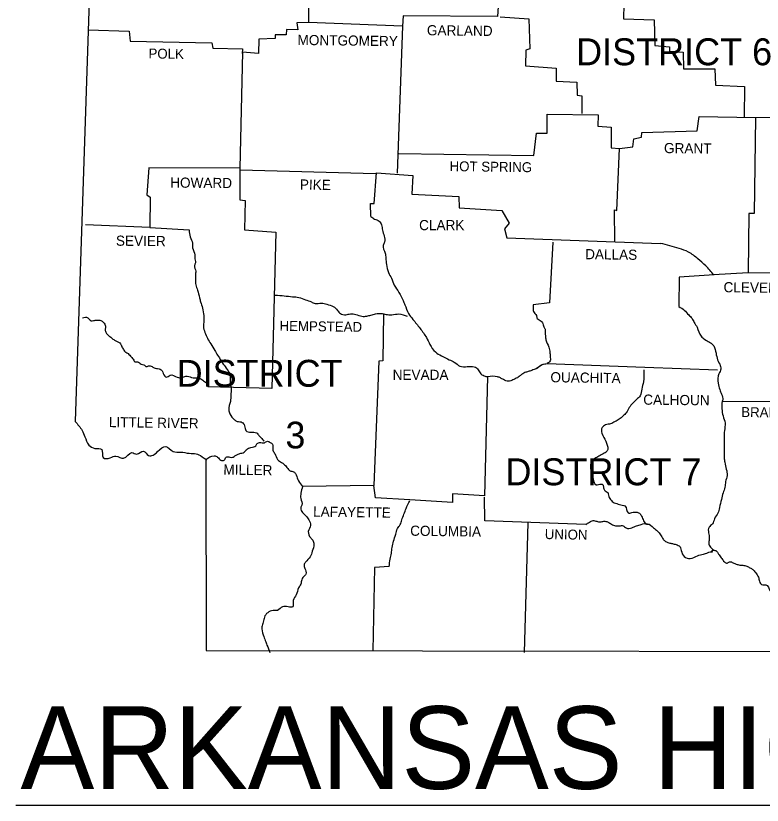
# Model space of a CAD drawing. Extents: x -33639 to 34530, y -17264 to 5867.
# Drawn here: x -17742 to -16002, y -10461 to -8621 of the extents above; entities that cross this region are included whole.
import ezdxf

# ---------------------------------------------------------------- set-up
doc = ezdxf.new("R2010")
doc.units = 0
for name, color, linetype in [('1', 7, 'Continuous'), ('2', 7, 'Continuous'), ('3', 7, 'Continuous'), ('S_MISC_BOUNDARY', 7, 'Continuous')]:
    doc.layers.add(name, color=color, linetype=linetype)

msp = doc.modelspace()

# ---------------------------------------------------------------- linework, layer by layer
at = {"layer": '1'}
msp.add_line((-17741.9, -10460.7), (-14228.8, -10460.7), dxfattribs=at)
for points in [[(-17667.8, -7158.5), (-17553.9, -8073.2), (-17603.4, -9566.3)], [(-17058.6, -8314.8), (-17059.7, -8636.8), (-17087.2, -8637.3), (-17085, -8653.9), (-17111.4, -8653.3), (-17111.9, -8665.4), (-17137.8, -8665.4), (-17137.3, -8674.2), (-17175.8, -8675.3), (-17176.3, -8708.9), (-17213.8, -8705.6), (-17219.8, -8976.4), (-17431.7, -8975.8), (-17436.7, -9038.6), (-17428.9, -9044.1), (-17429.5, -9114.5), (-17579.7, -9107.9)], [(-16434.5, -8557), (-16614.4, -8551.5), (-16619.4, -8622.5), (-16839.5, -8621.4), (-16840.6, -8645.1)], [(-16385.5, -8555.3), (-16323.8, -8559.2), (-16326, -8628), (-16253.9, -8630.7), (-16252.8, -8690.7), (-16218.7, -8693.5), (-16218.7, -8703.9), (-16186.8, -8706.1), (-16185.7, -8744.7), (-16113.1, -8744.7), (-16110.9, -8782.6), (-16043.7, -8785.9), (-16044.3, -8857.5)], [(-16612.8, -8623.6), (-16546.2, -8628.5), (-16544, -8697.9), (-16553.3, -8701.2), (-16554.4, -8738.1), (-16482.3, -8743), (-16482.3, -8773.3), (-16434.5, -8776), (-16433.9, -8806.3), (-16422.4, -8808), (-16422.9, -8848.7)], [(-16840.6, -8645.1), (-17059.7, -8636.8)], [(-16840.6, -8645.1), (-16853.3, -8987.9)], [(-17573.1, -8653.9), (-17477.9, -8657.2), (-17475.7, -8680.3), (-17285.3, -8684.1), (-17283.1, -8696.2), (-17213.8, -8698.4), (-17214.3, -8708.9)], [(-16849.4, -8942.2), (-16534.6, -8946.6), (-16528.6, -8894.4), (-16503.8, -8894.4), (-16503.3, -8850.3), (-16384.4, -8852), (-16385.5, -8878.4), (-16354.7, -8880.6), (-16354.7, -8929), (-16334.8, -8930.7)], [(-16017.8, -8859.1), (-16021.1, -9081.5), (-16033.8, -9082), (-16035.4, -9219.5)], [(-17219.8, -8976.4), (-17219.8, -9049.6), (-17207.7, -9051.8), (-17208.8, -9120), (-17136.2, -9125.5), (-17145, -9489.3), (-17294.7, -9485.4)], [(-17218.7, -8980.2), (-16903.9, -8988.5)], [(-16914.4, -9089.2), (-16915.5, -9058.9), (-16906.7, -9058.4), (-16901.2, -8987.4), (-16816.4, -8992.9), (-16818.6, -9036.4), (-16709.1, -9042.4), (-16708.5, -9068.8), (-16609.5, -9074.9), (-16592.4, -9104.6), (-16602.9, -9117.8), (-16597.9, -9138.2), (-16239.1, -9151.4)], [(-17429.5, -9114.5), (-17338.1, -9120)], [(-16490, -9148.6), (-16498.3, -9290.1), (-16536.3, -9294.5)], [(-16114.7, -9225.1), (-16196.2, -9230.1), (-16196.7, -9298.9)], [(-16885.2, -9315.4), (-16886.3, -9424.9), (-16896.2, -9426), (-16907.2, -9716)], [(-16503.8, -9431.5), (-16276, -9439.8), (-16107, -9446.4)], [(-16642.5, -9462.3), (-16649.6, -9739.7), (-16723.9, -9734.8), (-16724.5, -9755.1), (-16823.6, -9749.1)], [(-16096, -9519.6), (-15847.2, -9519)], [(-17299.1, -9655), (-17298, -10100.2), (-15280.9, -10103.5)], [(-16823.6, -9749.1), (-16903.4, -9744.7), (-16907.2, -9716), (-17074, -9717.7)], [(-16413.5, -9806.9), (-16648.5, -9798), (-16649.6, -9742.5)], [(-16548.4, -9803), (-16557.2, -10105.1)], [(-16872, -9904.8), (-16906.1, -9907), (-16910, -10100.7)]]:
    msp.add_lwpolyline(points, dxfattribs=at)
for points in [[(-16914.4, -9089.2), (-16905.6, -9094.7), (-16895.1, -9099.6), (-16889.6, -9107.9), (-16887.4, -9120.6), (-16883.5, -9134.3), (-16882.4, -9148.6), (-16885.7, -9156.3), (-16881.3, -9173.9), (-16879.7, -9186.1), (-16878, -9200.4), (-16873.6, -9219.6), (-16866.5, -9232.8), (-16859.9, -9248.8), (-16848.9, -9265.9), (-16839.5, -9284.6), (-16835.1, -9294.5), (-16826.9, -9314.8), (-16816.4, -9328.6), (-16799.9, -9349.5), (-16785, -9371), (-16776.8, -9386.9), (-16764.1, -9404.5), (-16749.8, -9413.3), (-16731.6, -9422.7), (-16720.1, -9428.2), (-16706.9, -9437.6), (-16689.8, -9438.7), (-16677.2, -9438.7), (-16665.6, -9443.6), (-16660.1, -9453.5), (-16650.2, -9460.1), (-16642.5, -9462.3)], [(-17338.1, -9120), (-17335.4, -9136.5), (-17330.4, -9150.8), (-17329.9, -9161.8), (-17324.9, -9178.3), (-17324.9, -9184.4), (-17323.3, -9196.5), (-17325.5, -9203.1), (-17322.7, -9216.3), (-17323.3, -9226.2), (-17323.3, -9234.5), (-17322.7, -9248.2), (-17318.3, -9260.3), (-17313.9, -9278.5), (-17311.2, -9287.9), (-17306.8, -9302.2), (-17304, -9319.8), (-17303.5, -9333), (-17304.6, -9345.1), (-17301.3, -9358.9), (-17295.2, -9372.6), (-17287.5, -9385.8), (-17278.2, -9400.7), (-17271.5, -9412.2), (-17263.3, -9424.9), (-17256.7, -9435.4), (-17246.8, -9448.6), (-17242.4, -9459.6), (-17242.4, -9475), (-17240.2, -9489.3), (-17240.7, -9505.3), (-17241.8, -9519.6), (-17245.7, -9539.4), (-17242.9, -9548.7), (-17232.5, -9562.5), (-17225.9, -9566.3), (-17214.3, -9568.5), (-17208.8, -9576.3), (-17205.5, -9587.8), (-17193.9, -9591.7), (-17181.3, -9592.8), (-17175.2, -9599.4), (-17167, -9608.2), (-17164.2, -9612.6)], [(-17137.3, -9271.9), (-17116.3, -9273.6), (-17097.1, -9275.8), (-17082.2, -9277.4), (-17066.8, -9282.9), (-17053.1, -9287.9), (-17044.3, -9291.7), (-17029.4, -9290.6), (-17016.7, -9293.4), (-17002.4, -9298.3), (-16992, -9307.7), (-16985.4, -9314.8), (-16972.7, -9317.6), (-16962.2, -9315.9), (-16949.6, -9317), (-16935.3, -9321.4), (-16923.7, -9320.9), (-16914.4, -9318.7), (-16903.4, -9315.9), (-16889.6, -9314.8), (-16879.1, -9317), (-16865.4, -9317.6), (-16849.4, -9315.9), (-16829.6, -9321.4)], [(-16536.3, -9294.5), (-16536.3, -9304.9), (-16532.4, -9314.8), (-16528.6, -9319.2), (-16526.9, -9326.4), (-16522, -9329.7), (-16514.8, -9336.3), (-16511, -9345.7), (-16508.2, -9351.7), (-16508.2, -9359.4), (-16507.7, -9367.1), (-16506.6, -9376.5), (-16500, -9393), (-16498.3, -9399.6), (-16497.2, -9405.1), (-16496.6, -9414.4), (-16496.6, -9425.5), (-16503.8, -9431.5)], [(-16196.7, -9298.9), (-16184, -9307.1), (-16173.6, -9318.1), (-16165.9, -9326.4), (-16160.9, -9335.7), (-16154.3, -9346.8), (-16145, -9367.7), (-16136.7, -9374.8), (-16125.2, -9382), (-16118, -9386.9), (-16110.9, -9402.9), (-16107.5, -9418.9), (-16101.5, -9433.2), (-16098.7, -9444.2), (-16103.7, -9455.2), (-16104.8, -9477.2), (-16101.5, -9492), (-16097.1, -9503.1), (-16094.3, -9515.7), (-16096, -9519.6)], [(-17586.3, -9325.3), (-17574.2, -9324.7), (-17566, -9331.9), (-17561, -9331.3), (-17552.2, -9330.2), (-17544, -9330.8), (-17537.9, -9335.7), (-17533, -9344.6), (-17533.5, -9352.8), (-17533, -9356.1), (-17529.1, -9363.3), (-17522.5, -9368.8), (-17515.4, -9374.3), (-17508.7, -9378.7), (-17497.7, -9385.8), (-17496.6, -9388), (-17492.2, -9396.8), (-17486.7, -9404), (-17480.1, -9408.4), (-17473, -9416.1), (-17469.7, -9419.4), (-17464.2, -9427.1), (-17458.1, -9427.7), (-17449.9, -9432.6), (-17443.8, -9434.3), (-17437.2, -9438.7), (-17430.6, -9436.5), (-17422.3, -9439.8), (-17411.3, -9443.1), (-17405.3, -9444.2), (-17398.1, -9454.6), (-17391, -9463.4), (-17382.2, -9458.5), (-17365.7, -9463.4), (-17355.2, -9464), (-17345.8, -9461.2), (-17338.7, -9461.8), (-17325.5, -9465.1), (-17317.2, -9465.1), (-17308.4, -9468.4), (-17300.2, -9475), (-17294.7, -9482.1), (-17294.7, -9485.4)], [(-16514.3, -9433.7), (-16528.6, -9443.1), (-16539.6, -9447.5), (-16547.8, -9450.2), (-16555.5, -9452.4), (-16565.4, -9459), (-16573.1, -9464.5), (-16583.6, -9469.5), (-16593.5, -9472.8), (-16605.6, -9468.9), (-16612.2, -9465.1), (-16619.4, -9462.3), (-16642.5, -9462.3)], [(-16528.6, -9443.1), (-16514.3, -9433.7), (-16503.8, -9431.5)], [(-16278.2, -9446.4), (-16279.3, -9473.9), (-16283.1, -9490.9), (-16287, -9506.4), (-16295.2, -9515.2), (-16304, -9524), (-16312.3, -9533.9), (-16319.4, -9546), (-16326.6, -9553.7), (-16335.9, -9561.4), (-16345.3, -9566.9), (-16355.8, -9571.8), (-16367.3, -9574.6), (-16375.6, -9580.7), (-16376.1, -9593.9), (-16366.8, -9612.6), (-16363.5, -9621.4), (-16362.4, -9631.8), (-16366.2, -9637.9), (-16375, -9642.8), (-16385.5, -9648.9), (-16394.8, -9654.4), (-16401.4, -9663.8), (-16402.5, -9676.4), (-16398.1, -9691.3), (-16396.5, -9700.1), (-16389.3, -9713.8), (-16383.8, -9713.3), (-16373.9, -9713.8), (-16372.8, -9716.6), (-16372.3, -9719.3), (-16370.1, -9726.5), (-16361.8, -9732.6), (-16360.7, -9738.1), (-16355.8, -9748.5), (-16347.5, -9755.7), (-16341.4, -9757.9), (-16328.8, -9761.7), (-16322.2, -9763.4), (-16315, -9779.3), (-16306.2, -9778.8), (-16299.6, -9777.7), (-16288.6, -9780.4), (-16283.7, -9787), (-16278.7, -9798), (-16272.1, -9805.8), (-16267.7, -9805.8)], [(-16096, -9519.6), (-16093.8, -9553.7), (-16088.8, -9570.2), (-16090.5, -9587.8), (-16091, -9604.9), (-16091, -9620.3), (-16091, -9635.1), (-16091, -9650.6), (-16089.9, -9661.6), (-16086.1, -9677.5), (-16084.4, -9692.4), (-16087.7, -9706.7), (-16089.4, -9719.9), (-16093.8, -9733.1), (-16097.6, -9748), (-16102, -9767.2), (-16105.9, -9779.9), (-16113.6, -9793.1), (-16118.6, -9805.2), (-16126.3, -9812.9), (-16127.4, -9826.1), (-16125.7, -9838.2), (-16126.8, -9849.2), (-16123, -9859.7), (-16113.1, -9866.8)], [(-17603.4, -9566.3), (-17587.5, -9587.3), (-17580.8, -9602.1), (-17571.5, -9621.4), (-17557.7, -9629.1), (-17541.8, -9631.8), (-17538.5, -9650.6), (-17522, -9651.1), (-17508.7, -9647.2), (-17490.6, -9652.2), (-17471.3, -9639), (-17460.3, -9642.3), (-17444.4, -9635.7), (-17432.3, -9645.6), (-17411.3, -9636.8), (-17392.6, -9624.7), (-17375, -9636.2), (-17358, -9637.9), (-17337.6, -9640.6), (-17321.6, -9641.7), (-17307.3, -9648.9), (-17296.9, -9656.1), (-17299.1, -9655)], [(-17299.1, -9655), (-17279.8, -9646.7), (-17271.5, -9649.4), (-17264.4, -9656.6), (-17256.1, -9656.6), (-17251.7, -9650), (-17243.5, -9649.4), (-17236.9, -9650), (-17229.7, -9645.6), (-17223.7, -9642.8), (-17215.4, -9640.1), (-17209.4, -9637.9), (-17203.9, -9631.8), (-17193.9, -9626.9), (-17182.4, -9623), (-17179.1, -9617.5), (-17173.6, -9615.3), (-17162.6, -9615.9), (-17155.4, -9612.6), (-17149.4, -9615.3), (-17143.9, -9619.2), (-17142.8, -9633.5), (-17138.4, -9641.2), (-17131.8, -9655), (-17122.4, -9662.1), (-17113.6, -9669.3), (-17110.3, -9673.7), (-17100.9, -9681.9), (-17092.7, -9684.7), (-17088.8, -9690.7), (-17082.8, -9705), (-17074, -9717.7)], [(-17074, -9717.7), (-17077.3, -9733.7), (-17077.8, -9746.3), (-17075.1, -9761.2), (-17077.8, -9768.3), (-17073.4, -9778.8), (-17065.2, -9787), (-17059.1, -9795.8), (-17055.3, -9808.5), (-17060.2, -9822.8), (-17054.7, -9837.7), (-17049.8, -9843.2), (-17047, -9852), (-17050.9, -9869), (-17055.8, -9881.7), (-17066.8, -9894.4), (-17070.1, -9900.4), (-17068.5, -9908.7), (-17065.7, -9921.9), (-17068.5, -9925.7), (-17075.6, -9935.1), (-17077.8, -9945.5), (-17082.8, -9954.3), (-17088.3, -9970.3), (-17095.4, -9983.5), (-17096.5, -9998.4), (-17107.5, -9998.4), (-17120.2, -9998.4), (-17131.8, -10006.6), (-17142.2, -10007.2), (-17154.9, -10012.1), (-17162.6, -10022.6), (-17165.3, -10034.1), (-17168.6, -10045.2), (-17165.3, -10063.9), (-17160.4, -10077.1), (-17156.5, -10087.5), (-17149.9, -10104.6)], [(-16872, -9904.8), (-16869.2, -9887.2), (-16866.5, -9873.4), (-16864.8, -9860.2), (-16861.5, -9845.4), (-16856.6, -9829.4), (-16852.2, -9816.2), (-16846.1, -9806.9), (-16842.3, -9795.8), (-16837.3, -9782.6), (-16832.4, -9768.9), (-16823.6, -9751.3)], [(-16413.5, -9806.9), (-16404.7, -9800.8), (-16396.5, -9797.5), (-16388.2, -9799.1), (-16379.4, -9800.2), (-16371.7, -9799.1), (-16361.8, -9800.8), (-16353.6, -9805.8), (-16344.2, -9809.6), (-16334.8, -9809.6), (-16326.6, -9809.6), (-16319.4, -9814.6), (-16306.2, -9814), (-16295.2, -9809.6), (-16284.2, -9806.3), (-16269.4, -9804.6), (-16256.1, -9814), (-16246.8, -9821.7), (-16239.1, -9830.5), (-16233.6, -9840.4), (-16227.5, -9845.9), (-16217.6, -9849.8), (-16209.9, -9851.4), (-16200.6, -9854.2), (-16195.6, -9856.4), (-16191.2, -9866.8), (-16184, -9881.1), (-16170.3, -9886.1), (-16153.2, -9879.5), (-16139.5, -9875.6), (-16129.6, -9872.3), (-16123.5, -9870.1), (-16118, -9869.6), (-16119.7, -9868.5), (-16113.1, -9866.8), (-16107, -9871.2), (-16103.1, -9877.3), (-16096.5, -9886.1), (-16090.5, -9893.8), (-16084.4, -9896.6), (-16078.4, -9893.3), (-16070.1, -9896), (-16063, -9898.8), (-16054.7, -9901), (-16047.6, -9901.5), (-16038.2, -9903.7), (-16031, -9907.6), (-16024.4, -9911.4), (-16017.8, -9918.6), (-16011.2, -9929.6), (-16009, -9938.4), (-16001.3, -9947.2), (-15994.2, -9947.2), (-15983.7, -9961.5), (-15979.9, -9967), (-15971.6, -9976.9), (-15965.6, -9976.9), (-15954, -9979.1)]]:
    msp.add_spline(points, degree=3, dxfattribs=at)
at = {"layer": 'S_MISC_BOUNDARY'}
for points in [[(-16017.8, -8858), (-15596.8, -8856.4), (-15595.7, -8788.7), (-15387.7, -8794.2)], [(-16345.9, -9148.1), (-16346.4, -9073.2), (-16341.4, -9074.9), (-16334.8, -8930.7), (-16304, -8926.3), (-16301.8, -8907.6), (-16283.7, -8904.3), (-16282.6, -8893.3), (-16154.3, -8889.4), (-16149.4, -8855.8), (-16017.8, -8858)], [(-15864.8, -9679.7), (-15852.7, -9672), (-15847.2, -9519), (-15850.5, -9290.6), (-15839, -9290.1), (-15839.5, -9221.3), (-15839.5, -9221.3), (-16035.5, -9220.2), (-16115.8, -9225.1)]]:
    msp.add_lwpolyline(points, dxfattribs=at)
msp.add_spline([(-16114.9, -9225.1), (-16134, -9203.7), (-16152.1, -9187.7), (-16174.1, -9171.7), (-16196.2, -9163.5), (-16239.1, -9151.4)], degree=3, dxfattribs=at)

# ---------------------------------------------------------------- texts
at = {"layer": '2'}
for s, height, rotation, p in [('GARLAND', 23.67, 359.3658, (-16783.9, -8666.5)), ('MONTGOMERY', 23.67, 359.2944, (-17085.5, -8689.1)), ('POLK', 23.11, 359.2152, (-17432.8, -8720.5)), ('GRANT', 23.67, 359.4032, (-16231.4, -8941.1)), ('HOT SPRING', 23.11, 359.2216, (-16731.1, -8983)), ('HOWARD', 23.67, 359.5145, (-17382.2, -9021.5)), ('PIKE', 23.66, 359.0452, (-17080, -9025.9)), ('SEVIER', 23.67, 359.4271, (-17508.7, -9156.9)), ('DALLAS', 23.66, 359.2462, (-16415.2, -9188.3)), ('CLEVELAND', 23.67, 359.3377, (-16092.7, -9265.3)), ('HEMPSTEAD', 23.11, 359.1885, (-17127.4, -9355)), ('OUACHITA', 23.67, 359.2043, (-16496.1, -9475)), ('CALHOUN', 23.67, 359.3634, (-16279.8, -9527.3)), ('BRADLEY', 23.11, 359.1449, (-16051.4, -9555.9)), ('LITTLE RIVER', 23.666, 359.1697, (-17525.3, -9579.6)), ('MILLER', 23.66, 359.1319, (-17258.3, -9690.2)), ('LAFAYETTE', 23.66, 359.1839, (-17049.2, -9788.1)), ('COLUMBIA', 23.66, 359.2125, (-16823, -9832.7)), ('UNION', 23.11, 358.9584, (-16509.3, -9840.4))]:
    msp.add_text(s, height=height, rotation=rotation, dxfattribs=at).set_placement(p)
for s, height, p in [('CLARK', 23.67, (-16802, -9120.7)), ('NEVADA', 23.67, (-16863.7, -9469.5)), ('ARKANSAS HIGHWAY DISTRICT 2', 192.623, (-17730.9, -10422.7))]:
    msp.add_text(s, height=height, dxfattribs=at).set_placement(p)
at = {"layer": '3'}
for s, height, p in [('DISTRICT 6', 62.74, (-16436.1, -8736.4)), ('DISTRICT', 62.74, (-17367.1, -9485.6)), ('3', 62.2, (-17113.4, -9629.2)), ('DISTRICT 7', 62.74, (-16600.8, -9715.1))]:
    msp.add_text(s, height=height, dxfattribs=at).set_placement(p)

doc.saveas('drawing.dxf')
